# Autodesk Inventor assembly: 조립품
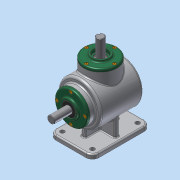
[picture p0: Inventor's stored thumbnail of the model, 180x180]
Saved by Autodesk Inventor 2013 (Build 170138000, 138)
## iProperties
Created: 2016-09
Part Number: 조립품
Document SubType Name: Assembly
Designer: Administrator
Author: Administrator
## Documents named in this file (14)
- C:\Users\Administrator\Desktop\460908V1009\답안조립품.iam
- C:\Users\Administrator\Desktop\460908V1009\본체.ipt
- C:\Users\Administrator\Desktop\460908V1009\커버.ipt
- C:\Users\Administrator\Desktop\460908V1009\M4.ipt
- C:\Users\Administrator\Desktop\460908V1009\베어링 6203.ipt
- C:\Users\Administrator\Desktop\460908V1009\메인 축.ipt
- 메인 축.ipt
- C:\Users\Administrator\Desktop\460908V1009\서브 축.ipt
- 서브 축.ipt
- C:\Users\Administrator\Desktop\460908V1009\오일실 17 32 8.ipt
- C:\Users\Administrator\Desktop\460908V1009\키 5x5.ipt
- C:\Users\Administrator\Desktop\460908V1009\키 4x4.ipt
- C:\Users\Administrator\Desktop\460908V1009\서브 베벨기어.ipt
- C:\Users\Administrator\Desktop\460908V1009\메인 베벨기어.ipt
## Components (8 placed, 1 different names)
1. M4:1
2. M4:3
3. M4:4
4. M4:5
5. M4:2
6. M4:6
7. M4:7
8. M4:8
